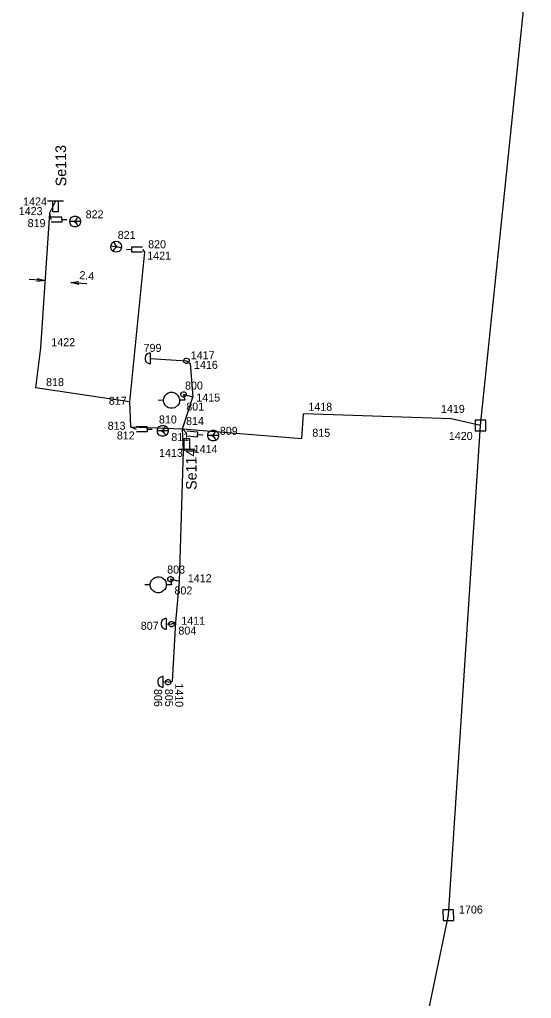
# Model space of a CAD drawing. Extents: x -535557 to -534097, y -1142175 to -1136716.
# Drawn here: x -534485.3 to -534437.3, y -1141185.6 to -1141093.9 of the extents above; entities that cross this region are included whole.
import ezdxf

# ---------------------------------------------------------------- set-up
doc = ezdxf.new("R2010")
doc.units = 0
doc.layers.add('Default', color=7, linetype='Continuous')
doc.layers.add('SS_SZDC', color=7, linetype='Continuous')

# ---------------------------------------------------------------- blocks, each defined once
blk = doc.blocks.new('POINT_DISPLAY')
at = {"layer": 'Default'}
blk.add_line((0, 0), (0, 0), dxfattribs=at)

msp = doc.modelspace()

# ---------------------------------------------------------------- linework, layer by layer
at = {"layer": 'SS_SZDC'}
for p, q in [((-534442.09, -1141131.899), (-534437.319, -1141085.829)), ((-534481.18, -1141110.889), (-534482.68, -1141110.889)), ((-534481.93, -1141110.889), (-534482.51, -1141112)), ((-534482.18, -1141111.889), (-534482.18, -1141110.889)), ((-534481.68, -1141110.889), (-534481.68, -1141111.889)), ((-534482.51, -1141112), (-534483.329, -1141124.62)), ((-534482.51, -1141112), (-534482.359, -1141112.6)), ((-534482.361, -1141112.35), (-534481.361, -1141112.343)), ((-534481.68, -1141111.889), (-534482.18, -1141111.889)), ((-534481.361, -1141112.343), (-534481.358, -1141112.843)), ((-534481.36, -1141112.593), (-534480.86, -1141112.59)), ((-534480.59, -1141112.693), (-534480.541, -1141112.542)), ((-534480.589, -1141112.893), (-534480.59, -1141112.693)), ((-534480.541, -1141112.542), (-534480.442, -1141112.392)), ((-534480.442, -1141112.392), (-534480.193, -1141112.29)), ((-534480.193, -1141112.29), (-534479.993, -1141112.289)), ((-534480.189, -1141112.79), (-534480.04, -1141112.689)), ((-534480.04, -1141112.689), (-534479.941, -1141112.539)), ((-534479.993, -1141112.289), (-534479.842, -1141112.338)), ((-534479.941, -1141112.539), (-534479.842, -1141112.338)), ((-534479.842, -1141112.338), (-534479.692, -1141112.437)), ((-534479.692, -1141112.437), (-534479.59, -1141112.686)), ((-534479.59, -1141112.686), (-534479.589, -1141112.886)), ((-534481.358, -1141112.843), (-534482.358, -1141112.849)), ((-534479.59, -1141112.786), (-534480.589, -1141112.793)), ((-534480.538, -1141113.042), (-534480.589, -1141112.893)), ((-534480.437, -1141113.192), (-534480.538, -1141113.042)), ((-534480.186, -1141113.29), (-534480.437, -1141113.192)), ((-534480.189, -1141112.79), (-534480.039, -1141112.889)), ((-534479.986, -1141113.289), (-534480.186, -1141113.29)), ((-534480.039, -1141112.889), (-534479.938, -1141113.039)), ((-534479.837, -1141113.238), (-534479.986, -1141113.289)), ((-534479.938, -1141113.039), (-534479.837, -1141113.238)), ((-534479.687, -1141113.137), (-534479.837, -1141113.238)), ((-534479.589, -1141112.886), (-534479.687, -1141113.137)), ((-534476.759, -1141115.173), (-534476.729, -1141114.976)), ((-534476.697, -1141115.436), (-534476.759, -1141115.173)), ((-534476.744, -1141115.075), (-534475.755, -1141115.224)), ((-534476.729, -1141114.976), (-534476.592, -1141114.743)), ((-534476.564, -1141115.557), (-534476.697, -1141115.436)), ((-534476.592, -1141114.743), (-534476.429, -1141114.667)), ((-534476.435, -1141115.374), (-534476.564, -1141115.557)), ((-534476.314, -1141115.241), (-534476.435, -1141115.374)), ((-534476.429, -1141114.667), (-534476.273, -1141114.64)), ((-534476.36, -1141114.88), (-534476.429, -1141114.667)), ((-534476.284, -1141115.043), (-534476.36, -1141114.88)), ((-534476.151, -1141115.164), (-534476.314, -1141115.241)), ((-534476.151, -1141115.164), (-534476.284, -1141115.043)), ((-534476.273, -1141114.64), (-534476.076, -1141114.67)), ((-534476.076, -1141114.67), (-534475.843, -1141114.807)), ((-534475.843, -1141114.807), (-534475.767, -1141114.97)), ((-534475.77, -1141115.323), (-534475.842, -1141115.464)), ((-534475.74, -1141115.126), (-534475.77, -1141115.323)), ((-534475.767, -1141114.97), (-534475.74, -1141115.126)), ((-534474.789, -1141115.426), (-534475.289, -1141115.429)), ((-534474.791, -1141115.176), (-534473.791, -1141115.17)), ((-534474.788, -1141115.676), (-534474.791, -1141115.176)), ((-534473.789, -1141115.42), (-534473.59, -1141115.629)), ((-534476.423, -1141115.629), (-534476.564, -1141115.557)), ((-534476.226, -1141115.659), (-534476.423, -1141115.629)), ((-534475.963, -1141115.597), (-534476.226, -1141115.659)), ((-534475.842, -1141115.464), (-534475.963, -1141115.597)), ((-534473.59, -1141115.629), (-534475, -1141129.7)), ((-534473.788, -1141115.669), (-534474.788, -1141115.676)), ((-534483.658, -1141118.125), (-534482.921, -1141118.327)), ((-534482.921, -1141118.327), (-534484.417, -1141118.222)), ((-534482.921, -1141118.327), (-534483.679, -1141118.424)), ((-534480.496, -1141118.498), (-534479.738, -1141118.402)), ((-534480.496, -1141118.498), (-534479, -1141118.604)), ((-534479.759, -1141118.701), (-534480.496, -1141118.498)), ((-534483.329, -1141124.62), (-534483.819, -1141128.36)), ((-534473.491, -1141125.362), (-534473.54, -1141125.513)), ((-534473.54, -1141125.513), (-534473.539, -1141125.713)), ((-534473.392, -1141125.212), (-534473.491, -1141125.362)), ((-534473.143, -1141125.11), (-534473.392, -1141125.212)), ((-534473.043, -1141125.11), (-534473.143, -1141125.11)), ((-534473.036, -1141126.109), (-534473.043, -1141125.11)), ((-534473.539, -1141125.713), (-534473.488, -1141125.862)), ((-534473.488, -1141125.862), (-534473.387, -1141126.012)), ((-534473.387, -1141126.012), (-534473.136, -1141126.11)), ((-534473.136, -1141126.11), (-534473.036, -1141126.109)), ((-534473.039, -1141125.61), (-534469.659, -1141125.84)), ((-534469.909, -1141125.79), (-534469.859, -1141125.69)), ((-534469.909, -1141125.89), (-534469.909, -1141125.79)), ((-534469.859, -1141125.99), (-534469.909, -1141125.89)), ((-534469.859, -1141125.69), (-534469.809, -1141125.64)), ((-534469.809, -1141126.04), (-534469.859, -1141125.99)), ((-534469.809, -1141125.64), (-534469.709, -1141125.59)), ((-534469.709, -1141126.09), (-534469.809, -1141126.04)), ((-534469.709, -1141125.59), (-534469.609, -1141125.59)), ((-534469.609, -1141126.09), (-534469.709, -1141126.09)), ((-534469.659, -1141125.84), (-534469.3, -1141126.079)), ((-534469.609, -1141125.59), (-534469.509, -1141125.64)), ((-534469.509, -1141126.04), (-534469.609, -1141126.09)), ((-534469.509, -1141125.64), (-534469.459, -1141125.69)), ((-534469.459, -1141125.99), (-534469.509, -1141126.04)), ((-534469.459, -1141125.69), (-534469.409, -1141125.79)), ((-534469.409, -1141125.89), (-534469.459, -1141125.99)), ((-534469.409, -1141125.79), (-534469.409, -1141125.89)), ((-534469.3, -1141126.079), (-534469.069, -1141129.26)), ((-534475, -1141129.7), (-534483.819, -1141128.36)), ((-534471.761, -1141129.242), (-534471.662, -1141129.092)), ((-534471.662, -1141129.092), (-534471.513, -1141128.941)), ((-534471.513, -1141128.941), (-534471.364, -1141128.84)), ((-534471.364, -1141128.84), (-534471.164, -1141128.788)), ((-534471.164, -1141128.788), (-534470.964, -1141128.787)), ((-534470.964, -1141128.787), (-534470.764, -1141128.836)), ((-534470.764, -1141128.836), (-534470.613, -1141128.935)), ((-534470.613, -1141128.935), (-534470.462, -1141129.084)), ((-534470.462, -1141129.084), (-534470.361, -1141129.233)), ((-534470.18, -1141128.941), (-534470.13, -1141128.841)), ((-534470.179, -1141129.041), (-534470.18, -1141128.941)), ((-534470.129, -1141129.141), (-534470.179, -1141129.041)), ((-534470.13, -1141128.841), (-534470.081, -1141128.79)), ((-534470.078, -1141129.19), (-534470.129, -1141129.141)), ((-534470.081, -1141128.79), (-534469.981, -1141128.74)), ((-534469.978, -1141129.24), (-534470.078, -1141129.19)), ((-534469.981, -1141128.74), (-534469.881, -1141128.739)), ((-534469.93, -1141128.989), (-534469.81, -1141129.53)), ((-534469.069, -1141129.26), (-534469.93, -1141128.989)), ((-534469.881, -1141128.739), (-534469.781, -1141128.789)), ((-534469.778, -1141129.189), (-534469.878, -1141129.239)), ((-534469.781, -1141128.789), (-534469.73, -1141128.838)), ((-534469.729, -1141129.138), (-534469.778, -1141129.189)), ((-534469.73, -1141128.838), (-534469.68, -1141128.938)), ((-534469.679, -1141129.038), (-534469.729, -1141129.138)), ((-534469.68, -1141128.938), (-534469.679, -1141129.038)), ((-534475, -1141129.7), (-534474.92, -1141132.02)), ((-534471.809, -1141129.543), (-534472.309, -1141129.546)), ((-534471.81, -1141129.443), (-534471.761, -1141129.242)), ((-534471.809, -1141129.643), (-534471.81, -1141129.443)), ((-534471.757, -1141129.842), (-534471.809, -1141129.643)), ((-534471.657, -1141129.992), (-534471.757, -1141129.842)), ((-534471.506, -1141130.141), (-534471.657, -1141129.992)), ((-534470.457, -1141129.984), (-534470.755, -1141130.236)), ((-534470.358, -1141129.833), (-534470.457, -1141129.984)), ((-534470.361, -1141129.233), (-534470.31, -1141129.433)), ((-534470.309, -1141129.633), (-534470.358, -1141129.833)), ((-534470.31, -1141129.433), (-534470.309, -1141129.533)), ((-534469.81, -1141129.53), (-534470.309, -1141129.533)), ((-534470.309, -1141129.533), (-534470.309, -1141129.633)), ((-534470.039, -1141132.209), (-534469.069, -1141129.26)), ((-534469.878, -1141129.239), (-534469.978, -1141129.24)), ((-534471.355, -1141130.24), (-534471.506, -1141130.141)), ((-534471.155, -1141130.288), (-534471.355, -1141130.24)), ((-534470.955, -1141130.287), (-534471.155, -1141130.288)), ((-534470.755, -1141130.236), (-534470.955, -1141130.287)), ((-534458.859, -1141133.11), (-534458.68, -1141130.799)), ((-534444.84, -1141131.28), (-534458.68, -1141130.799)), ((-534472.232, -1141132.002), (-534471.983, -1141131.9)), ((-534471.983, -1141131.9), (-534471.783, -1141131.899)), ((-534471.783, -1141131.899), (-534471.632, -1141131.948)), ((-534471.731, -1141132.149), (-534471.632, -1141131.948)), ((-534471.632, -1141131.948), (-534471.482, -1141132.047)), ((-534445.109, -1141177.78), (-534442.09, -1141131.899)), ((-534442.09, -1141131.899), (-534444.84, -1141131.28)), ((-534441.59, -1141131.399), (-534442.59, -1141131.399)), ((-534442.59, -1141131.399), (-534442.59, -1141132.399)), ((-534441.59, -1141132.399), (-534441.59, -1141131.399)), ((-534474.92, -1141132.02), (-534470.039, -1141132.209)), ((-534474.92, -1141132.02), (-534474.359, -1141132.26)), ((-534474.361, -1141132.01), (-534473.361, -1141132.003)), ((-534473.358, -1141132.503), (-534474.358, -1141132.509)), ((-534473.361, -1141132.003), (-534473.358, -1141132.503)), ((-534473.36, -1141132.253), (-534472.86, -1141132.25)), ((-534472.38, -1141132.303), (-534472.331, -1141132.152)), ((-534472.379, -1141132.503), (-534472.38, -1141132.303)), ((-534471.38, -1141132.396), (-534472.379, -1141132.403)), ((-534472.328, -1141132.652), (-534472.379, -1141132.503)), ((-534472.331, -1141132.152), (-534472.232, -1141132.002)), ((-534472.227, -1141132.802), (-534472.328, -1141132.652)), ((-534471.976, -1141132.9), (-534472.227, -1141132.802)), ((-534471.979, -1141132.4), (-534471.83, -1141132.299)), ((-534471.979, -1141132.4), (-534471.829, -1141132.499)), ((-534471.83, -1141132.299), (-534471.731, -1141132.149)), ((-534471.829, -1141132.499), (-534471.728, -1141132.649)), ((-534471.627, -1141132.848), (-534471.776, -1141132.899)), ((-534471.728, -1141132.649), (-534471.627, -1141132.848)), ((-534471.477, -1141132.747), (-534471.627, -1141132.848)), ((-534471.482, -1141132.047), (-534471.38, -1141132.296)), ((-534471.379, -1141132.496), (-534471.477, -1141132.747)), ((-534471.38, -1141132.296), (-534471.379, -1141132.496)), ((-534470.039, -1141132.209), (-534458.859, -1141133.11)), ((-534470.039, -1141132.209), (-534469.63, -1141132.659)), ((-534469.949, -1141134.28), (-534470.039, -1141132.209)), ((-534469.612, -1141132.41), (-534468.614, -1141132.482)), ((-534468.614, -1141132.482), (-534468.65, -1141132.981)), ((-534468.632, -1141132.731), (-534468.133, -1141132.767)), ((-534467.66, -1141132.753), (-534467.611, -1141132.602)), ((-534467.659, -1141132.953), (-534467.66, -1141132.753)), ((-534466.66, -1141132.846), (-534467.659, -1141132.853)), ((-534467.611, -1141132.602), (-534467.512, -1141132.452)), ((-534467.512, -1141132.452), (-534467.263, -1141132.35)), ((-534467.263, -1141132.35), (-534467.063, -1141132.349)), ((-534467.259, -1141132.85), (-534467.11, -1141132.749)), ((-534467.259, -1141132.85), (-534467.109, -1141132.949)), ((-534467.11, -1141132.749), (-534467.011, -1141132.599)), ((-534467.063, -1141132.349), (-534466.912, -1141132.398)), ((-534467.011, -1141132.599), (-534466.912, -1141132.398)), ((-534466.912, -1141132.398), (-534466.762, -1141132.497)), ((-534466.762, -1141132.497), (-534466.66, -1141132.746)), ((-534466.66, -1141132.746), (-534466.659, -1141132.946)), ((-534442.59, -1141132.399), (-534441.59, -1141132.399)), ((-534471.776, -1141132.899), (-534471.976, -1141132.9)), ((-534469.869, -1141134.129), (-534469.869, -1141133.129)), ((-534469.869, -1141133.129), (-534469.369, -1141133.129)), ((-534468.65, -1141132.981), (-534469.647, -1141132.909)), ((-534469.369, -1141133.129), (-534469.369, -1141134.129)), ((-534467.608, -1141133.102), (-534467.659, -1141132.953)), ((-534467.507, -1141133.252), (-534467.608, -1141133.102)), ((-534467.256, -1141133.35), (-534467.507, -1141133.252)), ((-534467.056, -1141133.349), (-534467.256, -1141133.35)), ((-534467.109, -1141132.949), (-534467.008, -1141133.099)), ((-534466.907, -1141133.298), (-534467.056, -1141133.349)), ((-534467.008, -1141133.099), (-534466.907, -1141133.298)), ((-534466.757, -1141133.197), (-534466.907, -1141133.298)), ((-534466.659, -1141132.946), (-534466.757, -1141133.197)), ((-534470.369, -1141134.129), (-534468.869, -1141134.129)), ((-534470.31, -1141146.53), (-534469.949, -1141134.28)), ((-534469.619, -1141134.129), (-534469.949, -1141134.28)), ((-534473.05, -1141146.733), (-534473.001, -1141146.532)), ((-534473.001, -1141146.532), (-534472.902, -1141146.382)), ((-534472.902, -1141146.382), (-534472.753, -1141146.231)), ((-534472.753, -1141146.231), (-534472.604, -1141146.13)), ((-534472.604, -1141146.13), (-534472.404, -1141146.078)), ((-534472.404, -1141146.078), (-534472.204, -1141146.077)), ((-534472.204, -1141146.077), (-534472.004, -1141146.126)), ((-534472.004, -1141146.126), (-534471.853, -1141146.225)), ((-534471.853, -1141146.225), (-534471.702, -1141146.374)), ((-534471.702, -1141146.374), (-534471.601, -1141146.523)), ((-534471.601, -1141146.523), (-534471.55, -1141146.723)), ((-534471.399, -1141146.249), (-534471.349, -1141146.149)), ((-534471.399, -1141146.349), (-534471.399, -1141146.249)), ((-534471.349, -1141146.449), (-534471.399, -1141146.349)), ((-534471.349, -1141146.149), (-534471.299, -1141146.099)), ((-534471.299, -1141146.499), (-534471.349, -1141146.449)), ((-534471.299, -1141146.099), (-534471.199, -1141146.049)), ((-534471.199, -1141146.549), (-534471.299, -1141146.499)), ((-534471.199, -1141146.049), (-534471.099, -1141146.049)), ((-534471.099, -1141146.549), (-534471.199, -1141146.549)), ((-534471.149, -1141146.299), (-534471.05, -1141146.819)), ((-534470.31, -1141146.53), (-534471.149, -1141146.299)), ((-534471.099, -1141146.049), (-534470.999, -1141146.099)), ((-534470.999, -1141146.499), (-534471.099, -1141146.549)), ((-534470.999, -1141146.099), (-534470.949, -1141146.149)), ((-534470.949, -1141146.449), (-534470.999, -1141146.499)), ((-534470.949, -1141146.149), (-534470.899, -1141146.249)), ((-534470.899, -1141146.349), (-534470.949, -1141146.449)), ((-534470.899, -1141146.249), (-534470.899, -1141146.349)), ((-534470.67, -1141150.34), (-534470.31, -1141146.53)), ((-534473.049, -1141146.833), (-534473.549, -1141146.836)), ((-534473.049, -1141146.933), (-534473.05, -1141146.733)), ((-534472.997, -1141147.132), (-534473.049, -1141146.933)), ((-534472.897, -1141147.282), (-534472.997, -1141147.132)), ((-534472.746, -1141147.431), (-534472.897, -1141147.282)), ((-534472.595, -1141147.53), (-534472.746, -1141147.431)), ((-534472.395, -1141147.578), (-534472.595, -1141147.53)), ((-534471.995, -1141147.526), (-534472.195, -1141147.577)), ((-534471.697, -1141147.274), (-534471.995, -1141147.526)), ((-534471.598, -1141147.123), (-534471.697, -1141147.274)), ((-534471.549, -1141146.923), (-534471.598, -1141147.123)), ((-534471.55, -1141146.723), (-534471.549, -1141146.823)), ((-534471.05, -1141146.819), (-534471.549, -1141146.823)), ((-534471.549, -1141146.823), (-534471.549, -1141146.923)), ((-534472.195, -1141147.577), (-534472.395, -1141147.578)), ((-534471.989, -1141150.229), (-534472.039, -1141150.379)), ((-534471.889, -1141150.079), (-534471.989, -1141150.229)), ((-534471.639, -1141149.979), (-534471.889, -1141150.079)), ((-534471.539, -1141149.979), (-534471.639, -1141149.979)), ((-534471.539, -1141150.979), (-534471.539, -1141149.979)), ((-534471.21, -1141150.31), (-534471.11, -1141150.26)), ((-534471.11, -1141150.26), (-534471.01, -1141150.26)), ((-534471.01, -1141150.26), (-534470.91, -1141150.31)), ((-534472.039, -1141150.379), (-534472.039, -1141150.579)), ((-534472.039, -1141150.579), (-534471.989, -1141150.729)), ((-534471.989, -1141150.729), (-534471.889, -1141150.879)), ((-534471.889, -1141150.879), (-534471.639, -1141150.979)), ((-534471.639, -1141150.979), (-534471.539, -1141150.979)), ((-534471.539, -1141150.479), (-534471.06, -1141150.51)), ((-534471.31, -1141150.46), (-534471.26, -1141150.36)), ((-534471.31, -1141150.56), (-534471.31, -1141150.46)), ((-534471.26, -1141150.66), (-534471.31, -1141150.56)), ((-534471.26, -1141150.36), (-534471.21, -1141150.31)), ((-534471.21, -1141150.71), (-534471.26, -1141150.66)), ((-534471.11, -1141150.76), (-534471.21, -1141150.71)), ((-534471.01, -1141150.76), (-534471.11, -1141150.76)), ((-534470.67, -1141150.34), (-534471.06, -1141150.51)), ((-534470.91, -1141150.71), (-534471.01, -1141150.76)), ((-534470.96, -1141155.85), (-534470.67, -1141150.34)), ((-534470.91, -1141150.31), (-534470.86, -1141150.36)), ((-534470.86, -1141150.66), (-534470.91, -1141150.71)), ((-534470.86, -1141150.36), (-534470.81, -1141150.46)), ((-534470.81, -1141150.56), (-534470.86, -1141150.66)), ((-534470.81, -1141150.46), (-534470.81, -1141150.56)), ((-534472.3, -1141155.68), (-534472.35, -1141155.83)), ((-534472.2, -1141155.53), (-534472.3, -1141155.68)), ((-534471.95, -1141155.43), (-534472.2, -1141155.53)), ((-534471.85, -1141155.43), (-534471.95, -1141155.43)), ((-534471.85, -1141156.43), (-534471.85, -1141155.43)), ((-534471.58, -1141155.809), (-534471.53, -1141155.759)), ((-534471.53, -1141155.759), (-534471.43, -1141155.709)), ((-534471.43, -1141155.709), (-534471.33, -1141155.709)), ((-534471.33, -1141155.709), (-534471.23, -1141155.759)), ((-534471.23, -1141155.759), (-534471.18, -1141155.809)), ((-534472.35, -1141155.83), (-534472.35, -1141156.03)), ((-534472.35, -1141156.03), (-534472.3, -1141156.18)), ((-534472.3, -1141156.18), (-534472.2, -1141156.33)), ((-534472.2, -1141156.33), (-534471.95, -1141156.43)), ((-534471.95, -1141156.43), (-534471.85, -1141156.43)), ((-534471.38, -1141155.959), (-534471.85, -1141155.93)), ((-534471.63, -1141155.909), (-534471.58, -1141155.809)), ((-534471.63, -1141156.009), (-534471.63, -1141155.909)), ((-534471.58, -1141156.109), (-534471.63, -1141156.009)), ((-534471.53, -1141156.159), (-534471.58, -1141156.109)), ((-534471.43, -1141156.209), (-534471.53, -1141156.159)), ((-534471.33, -1141156.209), (-534471.43, -1141156.209)), ((-534471.38, -1141155.959), (-534470.96, -1141155.85)), ((-534471.23, -1141156.159), (-534471.33, -1141156.209)), ((-534471.18, -1141156.109), (-534471.23, -1141156.159)), ((-534471.18, -1141155.809), (-534471.13, -1141155.909)), ((-534471.13, -1141156.009), (-534471.18, -1141156.109)), ((-534471.13, -1141155.909), (-534471.13, -1141156.009)), ((-534454.64, -1141223.729), (-534445.109, -1141177.78)), ((-534444.613, -1141177.276), (-534445.613, -1141177.283)), ((-534445.613, -1141177.283), (-534445.606, -1141178.283)), ((-534444.606, -1141178.276), (-534444.613, -1141177.276)), ((-534445.606, -1141178.283), (-534444.606, -1141178.276))]:
    msp.add_line(p, q, dxfattribs=at)

# ---------------------------------------------------------------- block references
for p in [(-534481.93, -1141110.889), (-534482.51, -1141112), (-534482.359, -1141112.6), (-534480.09, -1141112.79), (-534476.25, -1141115.149), (-534473.789, -1141115.42), (-534473.59, -1141115.629), (-534483.329, -1141124.62), (-534473.039, -1141125.61), (-534469.659, -1141125.84), (-534469.659, -1141125.84), (-534469.3, -1141126.079), (-534483.819, -1141128.36), (-534469.93, -1141128.989), (-534469.93, -1141128.989), (-534475, -1141129.7), (-534469.81, -1141129.53), (-534469.069, -1141129.26), (-534458.68, -1141130.799), (-534444.84, -1141131.28), (-534442.09, -1141131.899), (-534474.92, -1141132.02), (-534474.359, -1141132.26), (-534471.88, -1141132.399), (-534470.039, -1141132.209), (-534469.63, -1141132.659), (-534467.159, -1141132.85), (-534458.859, -1141133.11), (-534469.949, -1141134.28), (-534469.619, -1141134.129), (-534471.149, -1141146.299), (-534471.149, -1141146.299), (-534470.31, -1141146.53), (-534471.05, -1141146.819), (-534471.539, -1141150.479), (-534471.06, -1141150.51), (-534471.06, -1141150.51), (-534470.67, -1141150.34), (-534471.85, -1141155.93), (-534471.38, -1141155.959), (-534471.38, -1141155.959), (-534470.96, -1141155.85), (-534445.109, -1141177.78)]:
    msp.add_blockref('POINT_DISPLAY', p, dxfattribs=at)

# ---------------------------------------------------------------- texts
for s, height, rotation, p in [('Se113', 1, 90.37563, (-534480.923, -1141109.489)), ('2.4', 0.75, 355.96336, (-534479.722, -1141118.177)), ('Se114', 1, 90.37563, (-534468.7, -1141137.934)), ('806', 0.75, 270, (-534472.688, -1141156.589)), ('805', 0.75, 270, (-534471.664, -1141156.577)), ('1410', 0.75, 270, (-534470.713, -1141156.066))]:
    msp.add_text(s, height=height, rotation=rotation, dxfattribs=at).set_placement(p)
for s, p in [('1424', (-534484.971, -1141111.287)), ('1423', (-534485.382, -1141112.191)), ('822', (-534479.108, -1141112.491)), ('819', (-534484.548, -1141113.317)), ('821', (-534476.101, -1141114.42)), ('820', (-534473.251, -1141115.297)), ('1421', (-534473.334, -1141116.366)), ('1422', (-534482.329, -1141124.47)), ('799', (-534473.678, -1141125.006)), ('1417', (-534469.258, -1141125.7)), ('1416', (-534468.955, -1141126.597)), ('818', (-534482.819, -1141128.21)), ('800', (-534469.793, -1141128.533)), ('817', (-534476.94, -1141129.961)), ('1415', (-534468.738, -1141129.662)), ('801', (-534469.674, -1141130.509)), ('1418', (-534458.229, -1141130.518)), ('1419', (-534445.799, -1141130.718)), ('810', (-534472.238, -1141131.713)), ('813', (-534477.046, -1141132.305)), ('814', (-534469.697, -1141131.857)), ('812', (-534476.186, -1141133.212)), ('811', (-534471.08, -1141133.361)), ('809', (-534466.529, -1141132.776)), ('815', (-534457.859, -1141132.96)), ('1420', (-534445.062, -1141133.255)), ('1414', (-534468.987, -1141134.494)), ('1413', (-534472.229, -1141134.84)), ('803', (-534471.466, -1141145.775)), ('1412', (-534469.531, -1141146.584)), ('802', (-534470.781, -1141147.735)), ('807', (-534473.941, -1141151.042)), ('1411', (-534470.145, -1141150.579)), ('804', (-534470.416, -1141151.498)), ('1706', (-534444.109, -1141177.63))]:
    msp.add_text(s, height=0.75, dxfattribs=at).set_placement(p)

doc.saveas('drawing.dxf')
